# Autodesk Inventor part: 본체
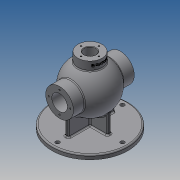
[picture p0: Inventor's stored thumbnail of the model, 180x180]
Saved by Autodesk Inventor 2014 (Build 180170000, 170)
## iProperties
Created: 2020-08
Part Number: 본체
Material: Generic
Document SubType Name: Modeling
Designer: kb542-5
Density: 1 g/cm^3
Appearance: Default
Author: kb542-5
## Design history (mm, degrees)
revolve "회전4" stored, may be unused: angle "d34" = 90 deg
node "작업 평면1"
revolve "회전5" stored, may be unused: angle "d35" = 90 deg
sketch "스케치2"
  geometry: L1 (-68, -31)-(68, -31) reference; L2 (-68, 31)-(68, 31) reference; L3 (-68, -31)-(-68, 31) reference; C1 r 85 at (0, 0); 2 further points; 1 other entity
  constraints: 1 centre point, 1 coincident, 1 other
  dimensions: "d5" = 170 diameter of C1
extrude "돌출1" join sketch "스케치2" distance "d6" = 10; taper "d7" = 0 deg
revolve "회전3" stored, may be unused: angle "d20" = 90 deg
node "작업 평면2"
sketch "스케치5"
  geometry: C1 r 27 at (0, 0); 1 further point
  constraints: 1 centre point, 1 coincident
  dimensions: "d22" = 54 diameter of C1
extrude "돌출3" join sketch "스케치5" stored distance "d23" = 10; taper "d24" = 0 deg
sketch "스케치6"
  geometry: 1 further point
sketch "스케치8"
  geometry: C1 r 31 at (0, 0) reference; C2 r 17.5 at (0, 0) reference
hole "구멍1" diameter "d38" = 26; stored, may be unused: countersink angle "d42" = 90 deg, drill point angle "d44" = 0 deg; dims "d36" = 10, "d37" = 10, "d39" = 6, "d40" = 4, "d41" = 2, "d43" = 8
sketch "스케치9"
  geometry: C1 r 13 at (0, 0) reference; 1 further point
  constraints: 1 vertical alignment
  dimensions: "d45" = 20 distance of point (0, 20) C1.centre
hole "구멍2" sketch "스케치9" at (0, 20) diameter "d46" = 3.242; stored, may be unused: countersink angle "d50" = 90 deg, drill point angle "d52" = 118 deg; dims "d47" = 12, "d48" = 4, "d49" = 2, "d51" = 15
sketch "스케치10"
  geometry: C1 r 17.5 at (0, 0) reference; 1 further point
  constraints: 1 horizontal alignment
  dimensions: "d56" = 24 distance of C1.centre point (-24, 0)
hole "구멍3" sketch "스케치10" at (-24, 0) diameter "d57" = 3.242; stored, may be unused: countersink angle "d61" = 90 deg, drill point angle "d63" = 118 deg; dims "d58" = 12, "d59" = 4, "d60" = 2, "d62" = 15
sketch "스케치3"
  geometry: L1 (-4, 43)-(4, 43); L2 (4, -43)-(-4, -43); L3 (-52, 4)-(52, 4); L4 (52, 4)-(52, -4); L5 (52, -4)-(-52, -4); L6 (-52, -4)-(-52, 4); L7 (-4, 43)-(-4, -43); L8 (4, 43)-(4, -43); C1 r 85 at (0, 0) reference; 5 further points
  constraints: 16 end point, 5 parallel, 4 midpoint, 3 horizontal alignment, 3 vertical alignment, 2 horizontal, 1 perpendicular
  dimensions: "d8" = 8 distance of L5.end L3.start; "d9" = 8 distance of L1.start L1.end; "d10" = 104 distance of L3.start L3.end; "d95" = 86 distance of L2.start L1.end
extrude "돌출4" join sketch "스케치3" stored distance "d67" = 10; taper "d68" = 0 deg
sketch "스케치11"
  geometry: C1 r 85 at (0, 0) reference; 1 further point
  constraints: 1 vertical alignment
  dimensions: "d69" = 72.5 distance of C1.centre point (0, 72.5)
hole "구멍4" sketch "스케치11" at (0, 72.5) diameter "d70" = 9; stored, may be unused: countersink angle "d74" = 90 deg, drill point angle "d76" = 118 deg; dims "d71" = 12, "d72" = 4, "d73" = 2, "d75" = 15
fillet "모깎기1" dims "d80" = 3
fillet "모깎기2" dims "d81" = 3
feature "결합1"
  node "솔리드1"
fillet "모깎기3" dims "d82" = 3
chamfer "모따기1" distance "d83" = 1; stored, may be unused: second distance "d84" = 2, angle "d85" = 45 deg
node "작업 평면3"
sketch "스케치12"
  geometry: L1 (-27, 65)-(27, 65) reference; L2 (-27, 65)-(-27, 47.286) reference; 2 further points
  constraints: 1 other
  dimensions: "d91" = 9 distance from line of point (0, 56) L1; "d92" = 27 distance from line of L2 point (0, 56)
feature "엠보싱1" sketch "스케치12" dims "d0" = 62, "d8" = 8, "d9" = 8, "d10" = 104, "d18" = 106, "d19" = 86, "d32" = 136, "d33" = 68, "d86" = 16, "d87" = 37, "d88" = 1.75, "d89" = 35, "d93" = 0.5, "d94" = 0, "d95" = 86
sketch "스케치13"
  geometry: C1 r 17.5 at (0, 0) reference
extrude "돌출5" join sketch "스케치13" stored distance "d96" = 10; taper "d97" = 0 deg
extrude "돌출6" join sketch "스케치3" stored distance "d98" = 10; taper "d99" = 0 deg
fillet "모깎기4" dims "d100" = 3
fillet "모깎기5" dims "d101" = 3
sketch "스케치1"
  geometry: L1 (-68, 31)-(-42.988, 31); L2 (68, 31)-(68, 17.5); L3 (-68, 17.5)-(-68, 31); L4 (68, 0)-(-68, 0); L5 (0, 53)-(0, -53); L6 (-50.027, 17.5)-(-39.278, 17.5); L7 (42.988, 31)-(68, 31); L8 (-42.988, 31)-(42.988, 31); L9 (39.278, 17.5)-(50.027, 17.5); L10 (-39.278, 17.5)-(39.278, 17.5); L11 (-52, 0)-(-50.25, 0); L12 (-50.25, 17.5)-(-50.25, 18.5); L13 (-50.25, 18.5)-(-52, 18.5); L14 (-52, 18.5)-(-52, 17.5); L15 (-68, 17.5)-(-50.25, 17.5); L16 (-50.25, 17.5)-(-39.278, 17.5); L17 (50.25, 17.5)-(50.25, 18.5); L18 (50.25, 18.5)-(52, 18.5); L19 (52, 18.5)-(52, 17.5); L20 (50.027, 17.5)-(50.25, 17.5); L21 (52, 17.5)-(68, 17.5); A1 r 53 centre (0, 0) between (0, 53) and (-42.988, 31); A2 r 43 centre (0, 0) between (0, 43) and (-29.799, 31); A3 r 53 centre (0, 0) between (0, -53) and (50.027, 17.5); A4 r 43 centre (0, 0) between (0, -43) and (39.278, 17.5); A5 r 53 centre (0, 0) between (-42.988, 31) and (-50.027, 17.5); A6 r 43 centre (0, 0) between (-29.799, 31) and (-39.278, 17.5); A7 r 43 centre (0, 0) between (-39.278, 17.5) and (0, -43); A8 r 43 centre (0, 0) between (29.799, 31) and (0, 43); A9 r 53 centre (0, 0) between (-50.027, 17.5) and (0, -53); A10 r 43 centre (0, 0) between (39.278, 17.5) and (29.799, 31); A11 r 53 centre (0, 0) between (50.027, 17.5) and (0, 53); 3 further points
  constraints: 42 end point, 24 point on circle, 11 centre point, 11 horizontal, 6 perpendicular, 6 point on line, 4 symmetric about line, 3 parallel, 2 coincident, 2 collinear, 2 midpoint, 2 vertical alignment, 2 other
  dimensions: "d0" = 62 diameter of L1 L4; "d18" = 106 diameter of A1; "d19" = 86 diameter of A2; "d32" = 136 distance between parallel lines of L2 L3; "d33" = 68 distance from line of point (0, 0) L3; "d86" = 16 distance between parallel lines of L14 L3; "d87" = 37 diameter of L13 L4; "d88" = 1.75 distance of L12.end L13.end; "d89" = 35 diameter of L15 L4
pattern_circular "원형 패턴1" dims angle "d54" = 360 deg
pattern_circular "원형 패턴2" dims angle "d65" = 360 deg
mirror "대칭1"
pattern_circular "원형 패턴3" dims angle "d78" = 360 deg
node "솔리드2"
other parameters: "d4" = -85, "d16" = 35, "d27" = 13.5, "d90" = -79
